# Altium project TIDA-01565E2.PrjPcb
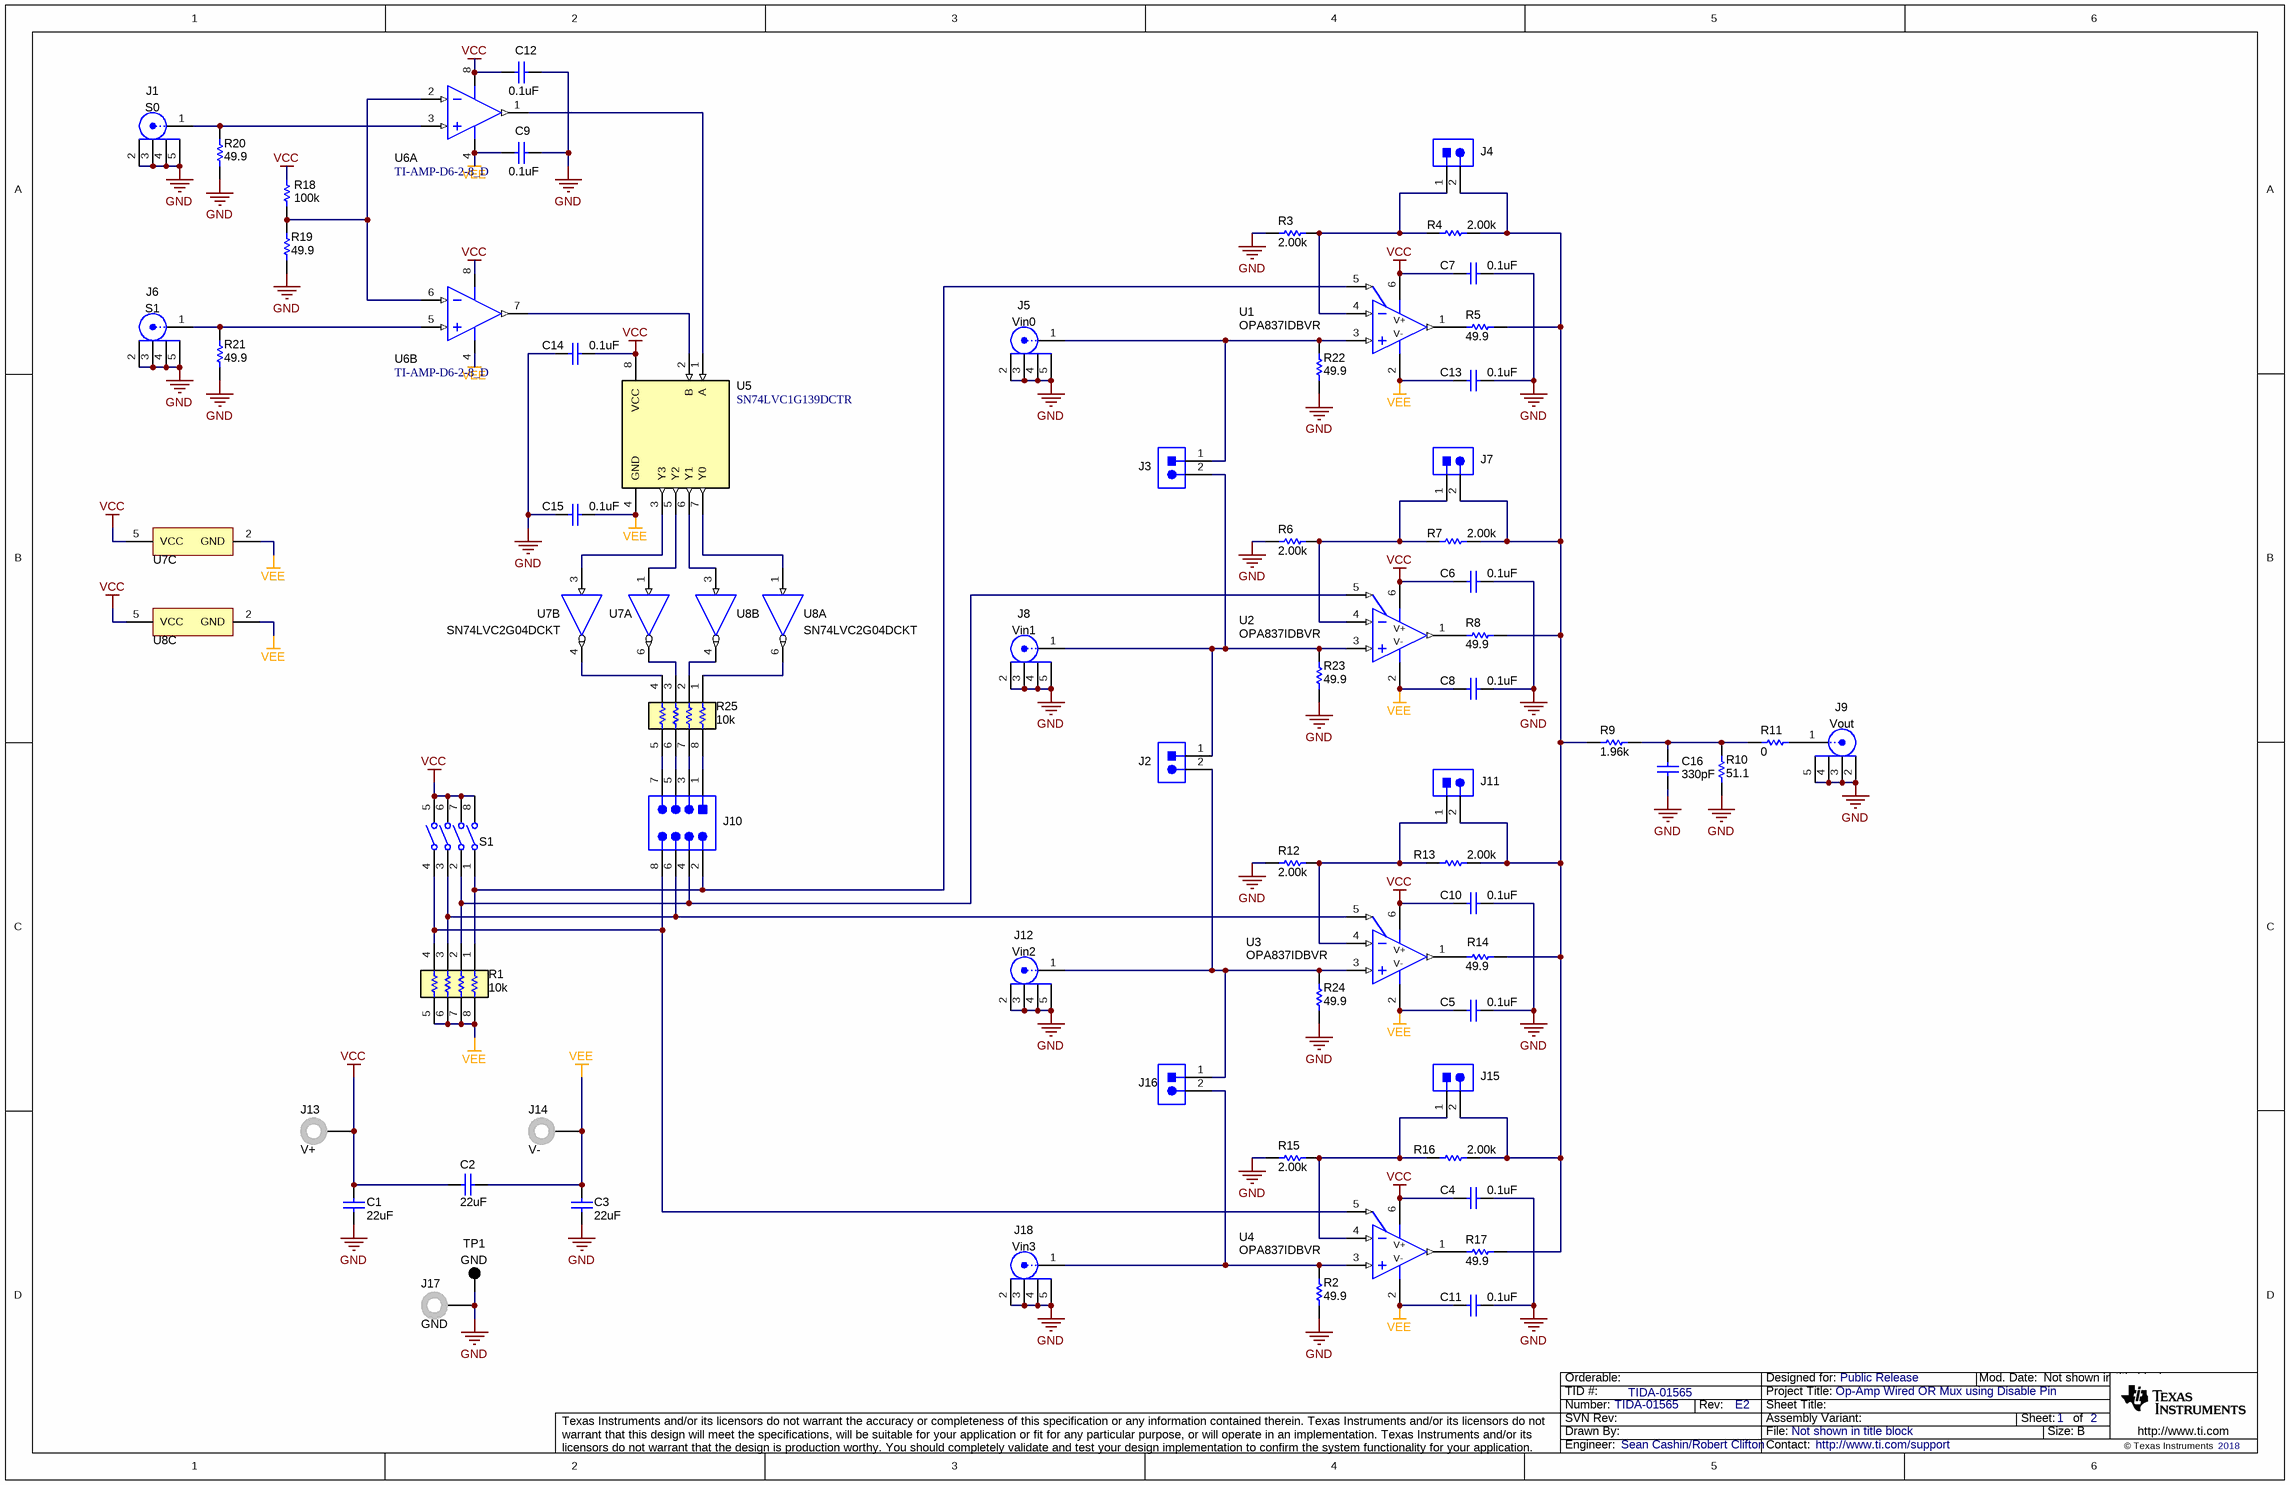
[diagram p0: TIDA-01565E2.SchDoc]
CopyrightYear: 2018; PCB_Layout: Bob Holtz; PCB_Rev: E2; PRJ_Customer: Public Release; PRJ_Engineer: Sean Cashin/Robert Clifton; PRJ_Number: TIDA-01565; PRJ_Title: Op-Amp Wired OR Mux using Disable Pin; SCH_Rev: E2; TechSupport: http://www.ti.com/support; TID: TIDA-01565
2 sheets, 106 parts. Net scope: global (net labels, ports and power ports of the same name join across sheets).
Board file: TIDA-01565E2.PcbDoc
Sheets:
  TIDA-01565E2.SchDoc
  TIDA-01565E2_Hardware.SchDoc

## Sheet TIDA-01565E2.SchDoc
size 431 x 279 mm; Date: Not shown in title block; ApprovedBy: Not shown in title block; CheckedBy: Not shown in title block; Author: Not shown in title block; CompanyName: Not shown in title block; Engineer: Not shown in title block; Organization: Not shown in title block; Address1: Not shown in title block; Address2: Not shown in title block; Address3: Not shown in title block; Address4: Not shown in title block; DocumentNumber: 1; Revision: Use project parameter SCH_Rev; SheetNumber: 1; SheetTotal: 2; PageSetup: Record=PageOptions¦CenterHorizontal=True¦CenterVertical=True¦PrintScale=1.00¦XCorrection=1.00¦YCorrection=1.00¦PrintKind=0¦BorderSize=5000000¦LeftOffset=0¦BottomOffset=0¦Orientation=2¦PaperLength=1000¦PaperWidth=1000¦Scale=100¦PaperSource=15¦PrintQuality=600¦MediaType=1¦DitherType=10¦PaperKind=Letter¦PrintScaleMode=1

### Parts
(Parts that share a designator on the sheet are numbered #1, #2 ... from top to bottom, then left to right.)
C1  ValueDisplayed: 22uF  [0603]  (hidden comment: Capacitor)
C2  ValueDisplayed: 22uF  [0603]  (hidden comment: Capacitor)
C3  ValueDisplayed: 22uF  [0603]  (hidden comment: Capacitor)
C4  ValueDisplayed: 0.1uF  [0402]  (hidden comment: Capacitor)
C5  ValueDisplayed: 0.1uF  [0402]  (hidden comment: Capacitor)
C6  ValueDisplayed: 0.1uF  [0402]  (hidden comment: Capacitor)
C7  ValueDisplayed: 0.1uF  [0402]  (hidden comment: Capacitor)
C8  ValueDisplayed: 0.1uF  [0402]  (hidden comment: Capacitor)
C9  ValueDisplayed: 0.1uF  [0402]  (hidden comment: Capacitor)
C10  ValueDisplayed: 0.1uF  [0402]  (hidden comment: Capacitor)
C11  ValueDisplayed: 0.1uF  [0402]  (hidden comment: Capacitor)
C12  ValueDisplayed: 0.1uF  [0402]  (hidden comment: Capacitor)
C13  ValueDisplayed: 0.1uF  [0402]  (hidden comment: Capacitor)
C14  ValueDisplayed: 0.1uF  [0402]  (hidden comment: Capacitor)
C15  ValueDisplayed: 0.1uF  [0402]  (hidden comment: Capacitor)
C16  ValueDisplayed: 330pF  [0603]  (hidden comment: Capacitor)
J1  S0  [Amphenol_901-10309]
J2  TSW-102-07-G-S  [TSW-102-07-X-S]  (value not drawn)
J3  TSW-102-07-G-S  [TSW-102-07-X-S]  (value not drawn)
J4  TSW-102-07-G-S  [TSW-102-07-X-S]  (value not drawn)
J5  Vin0  [Amphenol_901-10309]
J6  S1  [Amphenol_901-10309]
J7  TSW-102-07-G-S  [TSW-102-07-X-S]  (value not drawn)
J8  Vin1  [Amphenol_901-10309]
J9  Vout  [Amphenol_901-10309]
J10  TSW-104-07-G-D  [TSW-104-07-G-D]  (value not drawn)
J11  TSW-102-07-G-S  [TSW-102-07-X-S]  (value not drawn)
J12  Vin2  [Amphenol_901-10309]
J13  V+  [Keystone_6095]
J14  V-  [Keystone_6095]
J15  TSW-102-07-G-S  [TSW-102-07-X-S]  (value not drawn)
J16  TSW-102-07-G-S  [TSW-102-07-X-S]  (value not drawn)
J17  GND  [Keystone_6095]
J18  Vin3  [Amphenol_901-10309]
R1  ValueDisplayed: 10k  [TC164]  (hidden comment: RES_ARRAY_4x1)
R2  ValueDisplayed: 49.9  [0603]  (hidden comment: Resistor)
R3  ValueDisplayed: 2.00k  [0603]  (hidden comment: RT0603BRD072KL)
R4  ValueDisplayed: 2.00k  [0603]  (hidden comment: RT0603BRD072KL)
R5  ValueDisplayed: 49.9  [0603]  (hidden comment: Resistor)
R6  ValueDisplayed: 2.00k  [0603]  (hidden comment: RT0603BRD072KL)
R7  ValueDisplayed: 2.00k  [0603]  (hidden comment: RT0603BRD072KL)
R8  ValueDisplayed: 49.9  [0603]  (hidden comment: Resistor)
R9  ValueDisplayed: 1.96k  [0603]  (hidden comment: RC0603FR-071K96L)
R10  ValueDisplayed: 51.1  [0603]  (hidden comment: Resistor)
R11  ValueDisplayed: 0  [0603]  (hidden comment: RC0603JR-070RL)
R12  ValueDisplayed: 2.00k  [0603]  (hidden comment: RT0603BRD072KL)
R13  ValueDisplayed: 2.00k  [0603]  (hidden comment: RT0603BRD072KL)
R14  ValueDisplayed: 49.9  [0603]  (hidden comment: Resistor)
R15  ValueDisplayed: 2.00k  [0603]  (hidden comment: RT0603BRD072KL)
R16  ValueDisplayed: 2.00k  [0603]  (hidden comment: RT0603BRD072KL)
R17  ValueDisplayed: 49.9  [0603]  (hidden comment: Resistor)
R18  ValueDisplayed: 100k  [0603]  (hidden comment: Resistor)
R19  ValueDisplayed: 49.9  [0603]  (hidden comment: Resistor)
R20  ValueDisplayed: 49.9  [0603]  (hidden comment: Resistor)
R21  ValueDisplayed: 49.9  [0603]  (hidden comment: Resistor)
R22  ValueDisplayed: 49.9  [0603]  (hidden comment: Resistor)
R23  ValueDisplayed: 49.9  [0603]  (hidden comment: Resistor)
R24  ValueDisplayed: 49.9  [0603]  (hidden comment: Resistor)
R25  ValueDisplayed: 10k  [TC164]  (hidden comment: RES_ARRAY_4x1)
S1  SW_4SPST  [SW_219-4LPST]  (value not drawn)
TP1  GND  [Keystone5001]
U1  OPA837IDBVR  [DBV0006A_M]
U2  OPA837IDBVR  [DBV0006A_M]
U3  OPA837IDBVR  [DBV0006A_M]
U4  OPA837IDBVR  [DBV0006A_M]
U5  SN74LVC1G139DCTR  [DCT0008A_N]
U6  TI-AMP-D6-2-8_D  [D0008A_L]  (parts A,B of 2)
U7#1  SN74LVC2G04DCKT  [DCK0006A_N]  (value not drawn)  (part C of 3)
U7#2  SN74LVC2G04DCKT  [DCK0006A_N]  (value not drawn)  (parts A,B of 3)
U8#1  SN74LVC2G04DCKT  [DCK0006A_N]  (parts A,B of 3)
U8#2  SN74LVC2G04DCKT  [DCK0006A_N]  (value not drawn)  (part C of 3)

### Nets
GND: C1.2 C3.2 C4.2 C5.2 C6.2 C7.2 C8.2 C9.2 C10.2 C11.2 C12.2 C13.2 C14.1 C15.1 C16.2 J1.2 J1.3 J1.4 J1.5 J5.2 J5.3 J5.4 J5.5 J6.2 J6.3 J6.4 J6.5 J8.2 J8.3 J8.4 J8.5 J9.2 J9.3 J9.4 J9.5 J12.2 J12.3 J12.4 J12.5 J17.1 J18.2 J18.3 J18.4 J18.5 R2.1 R3.1 R6.1 R10.1 R12.1 R15.1 R19.1 R20.1 R21.1 R22.1 R23.1 R24.1 TP1.1
VCC: C1.1 C2.1 C4.1 C6.1 C7.1 C10.1 C12.1 C14.2 J13.1 R18.1 S1.5(B4) S1.6(B3) S1.7(B2) S1.8(B1) U1.6(V+) U2.6(V+) U3.6(V+) U4.6(V+) U5.8(VCC) U6.8(VCC+) U7#1.5(VCC) U8#2.5(VCC)
VEE: C2.2 C3.1 C5.1 C8.1 C9.1 C11.1 C13.1 C15.2 J14.1 R1.5 R1.6 R1.7 R1.8 U1.2(V-) U2.2(V-) U3.2(V-) U4.2(V-) U5.4(GND) U6.4(VCC-) U7#1.2(GND) U8#2.2(GND)
NetC16_1: C16.1 R9.2 R10.2 R11.1
NetJ1_1: J1.1 R20.2 U6.3(IN1+)
NetJ2_1: J2.1 J3.2 J8.1 R23.2 U2.3(IN+)
NetJ2_2: J2.2 J12.1 J16.1 R24.2 U3.3(IN+)
NetJ3_1: J3.1 J5.1 R22.2 U1.3(IN+)
NetJ4_1: J4.1 R3.2 R4.1 U1.4(IN-)
NetJ4_2: J4.2 J7.2 J11.2 J15.2 R4.2 R5.2 R7.2 R8.2 R9.1 R13.2 R14.2 R16.2 R17.2
NetJ6_1: J6.1 R21.2 U6.5(IN2+)
NetJ7_1: J7.1 R6.2 R7.1 U2.4(IN-)
NetJ9_1: J9.1 R11.2
NetJ10_1: J10.1 R25.8
NetJ10_2: J10.2 R1.1 S1.1(A1) U1.5(PD)
NetJ10_3: J10.3 R25.7
NetJ10_4: J10.4 R1.2 S1.2(A2) U2.5(PD)
NetJ10_5: J10.5 R25.6
NetJ10_6: J10.6 R1.3 S1.3(A3) U3.5(PD)
NetJ10_7: J10.7 R25.5
NetJ10_8: J10.8 R1.4 S1.4(A4) U4.5(PD)
NetJ11_1: J11.1 R12.2 R13.1 U3.4(IN-)
NetJ15_1: J15.1 R15.2 R16.1 U4.4(IN-)
NetJ16_2: J16.2 J18.1 R2.2 U4.3(IN+)
NetR5_1: R5.1 U1.1(OUT)
NetR8_1: R8.1 U2.1(OUT)
NetR14_1: R14.1 U3.1(OUT)
NetR17_1: R17.1 U4.1(OUT)
NetR18_2: R18.2 R19.2 U6.2(IN1-) U6.6(IN2-)
NetR25_1: R25.1 U8#1.6(1Y)
NetR25_2: R25.2 U8#1.4(2Y)
NetR25_3: R25.3 U7#2.6(1Y)
NetR25_4: R25.4 U7#2.4(2Y)
NetU5_1: U5.1(A) U6.1(OUT1)
NetU5_2: U5.2(B) U6.7(OUT2)
NetU5_3: U5.3(Y3) U7#2.3(2A)
NetU5_5: U5.5(Y2) U7#2.1(1A)
NetU5_6: U5.6(Y1) U8#1.3(2A)
NetU5_7: U5.7(Y0) U8#1.1(1A)

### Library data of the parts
C1-C3 = CMP-0007158-5: CAP, CERM, 22 uF, 10 V, +/- 20%, X5R, 0603; PartNumber: GRM187R61A226ME15D; Manufacturer: MuRata; Polarized: N; Value: 22uF; U/M: EA; Cap_F: 22µF; Value1: Unknown; VDC_V: 10V; TaMin_C: -55°C; TaMax_C: 85°C; SizeArea_mm2: 1.28; SizeAreaWB_mm2: 4.68; SizeX_mm: 1.6; SizeY_mm: 0.8; SizeZ_mm: 1; AEC Category: Q200
C4-C15 = CMP-0006259-2: CAP, CERM, 0.1 uF, 10 V, +/- 10%, X5R, 0402; PartNumber: C1005X5R1A104K050BA; Manufacturer: TDK; Polarized: N; Value: 0.1uF; U/M: EA; Cap_F: 100nF; Value1: Unknown; VDC_V: 10V; TaMin_C: -55°C; TaMax_C: 85°C; SizeArea_mm2: 0.5; SizeAreaWB_mm2: 3; SizeX_mm: 1; SizeZ_mm: 0.6; AEC Category: Q200
C16 = CMP-0006784-4: CAP, CERM, 330 pF, 50 V, +/- 5%, C0G/NP0, 0603; PartNumber: 06035A331JAT2A; Manufacturer: AVX; Polarized: N; Value: 330pF; U/M: EA; ESR_ohm: 0.071; Value1: 0.071 ohm; VDC_V: 50V; TaMin_C: -55°C; TaMax_C: 125°C; SizeArea_mm2: 1.28; SizeAreaWB_mm2: 4.68; SizeX_mm: 1.6; SizeY_mm: 0.8; SizeZ_mm: 1; AEC Category: Q200
J1 J5 J6 J8 J9 J12 J18 = CMP-0055840-1: SMA JACK 50 OHM EDGE MNT, SMT; Manufacturer: Amphenol-Tuchel Electronics; PartNumber: 901-10309; CNHeader: FALSE; ContactFinish: Gold; CT: TRUE
J2-J4 J7 J11 J15 J16 = CMP-0075405-1: Header, 100mil, 2x1, Gold, TH; Manufacturer: Samtec; Pitch_mm: 2.54; Cert_VDE: N; Gender: Male; Cert_CSA: Y; Voltage_V: 550V; Green_REACh: Passed; Current_A: 6.3A; CT: False; Green_Lifecycle: Active; Row_Count: 1; CNHeader: True
J10 = CMP-0075408-1: Header, 100mil, 4x2, Gold, TH; Manufacturer: Samtec; Pitch_mm: 2.54; Cert_VDE: N; Gender: Male; Cert_CSA: Y; Voltage_V: 550V; Green_REACh: Passed; Current_A: 6.3A; CT: False; Green_Lifecycle: Active; Row_Count: 2; CNHeader: True
J13 J14 J17 = CMP-0055169-2: Standard Banana Jack, Uninsulated; Manufacturer: Keystone; CT: TRUE; Green_REACh: Passed; CNHeader: FALSE; Green_Lifecycle: Active
R1 R25 = CMP-0015378-3: RES, 10 k, 5%, 0.0625 W, 3.2x1.6mm; PartNumber: TC164-JR-0710KL; Manufacturer: Yageo America; CompType: Resistor; Value: 10k; Value_Code: 10k0; Power_W: 62.5mW; TempCo: 200 ppm/C; EIA_Code: E24; U/M: EA; AEC Category: Q200; AEC Qualified: N
R2 R5 R8 R14 R17 R19-R24 = CMP-0022707-2: RES, 49.9, 1%, 0.1 W, AEC-Q200 Grade 0, 0603; PartNumber: ERJ-3EKF49R9V; Manufacturer: Panasonic; Value: 49.9; Value_Code: 49R9; Power_W: 100mW; Value2: 0.1W; TempCo: 100 ppm/C; SizeArea_mm2: 1.28; SizeX_mm: 1.6; SizeY_mm: 0.8; SizeZ_mm: 1; EIA_Code: E96; U/M: EA; AEC Category: Q200; AEC Qualified: Y; AEC Grade: 0
R3 R4 R6 R7 R12 R13 R15 R16 = CMP-0024089-3: RES, 2.00 k, 0.1%, 0.1 W, 0603; Manufacturer: Yageo America; Power_W: 100mW; TempCo: 25 ppm/C; Value_Code: 2k00; U/M: EA; Value: 2.00k; EIA_Code: E192; Res_ohm: 2k; SizeX_mm: 1.6; SizeY_mm: 0.8; SizeZ_mm: 1; Value2: 0.1W; SizeArea_mm2: 1.28; CompType: Resistor; VDC_V: 75V; AEC Category: Q200
R9 = CMP-0022894-3: RES, 1.96 k, 1%, 0.1 W, 0603; Manufacturer: Yageo America; Power_W: 100mW; TempCo: 200 ppm/C; Value_Code: 1k96; U/M: EA; Value: 1.96k; EIA_Code: E96; SizeX_mm: 1.6; SizeY_mm: 0.8; SizeZ_mm: 1; Value2: 0.1W; SizeArea_mm2: 1.28; CompType: Resistor; VDC_V: 150V; AEC Category: Q200
R10 = CMP-0023168-3: RES, 51.1, 1%, 0.1 W, 0603; PartNumber: RC0603FR-0751R1L; Manufacturer: Yageo America; Value: 51.1; Value_Code: 51R1; Power_W: 100mW; Value2: 0.1W; VDC_V: 150V; TempCo: 200 ppm/C; SizeArea_mm2: 1.28; SizeX_mm: 1.6; SizeY_mm: 0.8; SizeZ_mm: 1; EIA_Code: E96; U/M: EA; AEC Category: Q200
R11 = CMP-0025885-3: RES, 0, 5%, 0.1 W, 0603; Manufacturer: Yageo America; Power_W: 100mW; TempCo: 200 ppm/C; Value_Code: 0000; U/M: EA; Value: 0; EIA_Code: E24; SizeX_mm: 1.6; SizeZ_mm: 1; Value2: 0.1W; SizeArea_mm2: 1.28; CompType: Resistor; VDC_V: 50V; AEC Category: Q200; SizeY_mm: 0.8
R18 = CMP-0023630-3: RES, 100 k, 0.1%, 0.1 W, 0603; PartNumber: RT0603BRD07100KL; Manufacturer: Yageo America; Value: 100k; Power_W: 100mW; Value2: 0.1W; VDC_V: 75V; TempCo: 25 ppm/C; SizeArea_mm2: 1.28; SizeX_mm: 1.6; SizeY_mm: 0.8; SizeZ_mm: 1; EIA_Code: E192; U/M: EA; AEC Category: Q200
S1 = CMP-0002176-2: Switch, SPST 4 Pos, Top Actuated, SMT; PartNumber: 219-4LPST; Manufacturer: CTS Electrocomponents; VDC_V: 50V; SwitchFunction: Off-On; PositionCount: 4; CurrentRating_mA: 100A
TP1 = CMP-0055138-1: Test Point, Miniature, Black, TH; Manufacturer: Keystone; CNHeader: FALSE; Green_Lifecycle: Active; Green_REACh: Passed; ContactFinish: Silver; CT: TRUE
U1-U4 = CMP-0013237-2: Low Power, Precision, 105MHz, Voltage Feedback Op Amp, DBV0006A (SOT-6); Manufacturer: Texas Instruments; Alternate PartNumber: OPA837IDBVT; SizeX_mm: 2.8; SizeY_mm: 2.9; CompType: IC; SizeZ_mm: 1.45; SizeArea_mm2: 8.12; SizeAreaWB_mm2: 14.82; U/M: EA
U5 = CMP-0050973-1: 2-Line-to-4-Line Decoder, DCT0008A, LARGE T&R; Manufacturer: Texas Instruments; Bits(#): 1; Output Drive (IOL/IOH)(Max)(mA): 32/-32; Technology Family: LVC; tpd @ Nom Voltage(Max)(ns): 16.5,7.5,4.9,3.6; Rating: Catalog; Input Type: CMOS/TTL; F @ Nom Voltage(Max)(Mhz): 150; Voltage(Nom)(V): 1.8,2.5,3.3,5; Specialty Logic Family: Decoder/Encoder/Multiplexer; Schmitt Trigger: No; ICC @ Nom Voltage(Max)(mA): 0.01; Output Type: CMOS; VCC(Min)(V): 1.65; Logic: True; VCC(Max)(V): 5.5
U6 = CMP-0043405-1: Dual High-Performance, Low-Voltage Operational Amplifier, 2 to 5 V, -40 to 85 degC, 8-pin SOIC (D8), Green (RoHS & no Sb/Br); PartNumber: TLV2362ID; Manufacturer: Texas Instruments; CMRR(Min)(dB): 75; GBW(Typ)(MHz): 6; IIB(Max)(pA): 150000; Iq per channel(Max)(mA): 2.25; Number of Channels: 2; Slew Rate(Typ)(V/us): 2.5; Sub Family: General Purpose Amplifier, Low Noise Amp (<=10nV/rtHz), Low Supply Voltage Amplifier (<=2.7V); Total Supply Voltage(Max)(+5V is 5, +/-5V is 10): 5; Vn at 1kHz(Typ)(nV/rtHz): 9
U7#1 U7#2 U8#1 U8#2 = CMP-0051888-2: Dual Inverter, DCK0006A, SMALL T&R; Manufacturer: Texas Instruments; Output Type: CMOS; Bits(#): 2; Input Type: CMOS/TTL; Technology Family: LVC; Schmitt Trigger: No; VCC(Max)(V): 5.5; Sub-Family: Inverting Buffer/Driver; Rating: Catalog; Output Drive (IOL/IOH)(Max)(mA): 32/-32; ICC @ Nom Voltage(Max)(mA): 0.01; VCC(Min)(V): 1.65; F @ Nom Voltage(Max)(Mhz): 150; Logic: Inverting; Voltage(Nom)(V): 1.8,2.5,3.3,5; tpd @ Nom Voltage(Max)(ns): 8,4.9,4.6,3.7

## Sheet TIDA-01565E2_Hardware.SchDoc
size 431 x 279 mm; Date: Not shown in title block; ApprovedBy: Not shown in title block; CheckedBy: Not shown in title block; Author: Not shown in title block; CompanyName: Not shown in title block; Engineer: Not shown in title block; Organization: Not shown in title block; Address1: Not shown in title block; Address2: Not shown in title block; Address3: Not shown in title block; Address4: Not shown in title block; DocumentNumber: 2; Revision: Use project parameter SCH_Rev; SheetNumber: 2; SheetTotal: 2; PageSetup: Record=PageOptions¦CenterHorizontal=True¦CenterVertical=True¦PrintScale=1.00¦XCorrection=1.00¦YCorrection=1.00¦PrintKind=0¦BorderSize=5000000¦LeftOffset=0¦BottomOffset=0¦Orientation=2¦PaperLength=1000¦PaperWidth=1000¦Scale=100¦PaperSource=15¦PrintQuality=600¦MediaType=1¦DitherType=10¦PaperKind=Letter¦PrintScaleMode=1
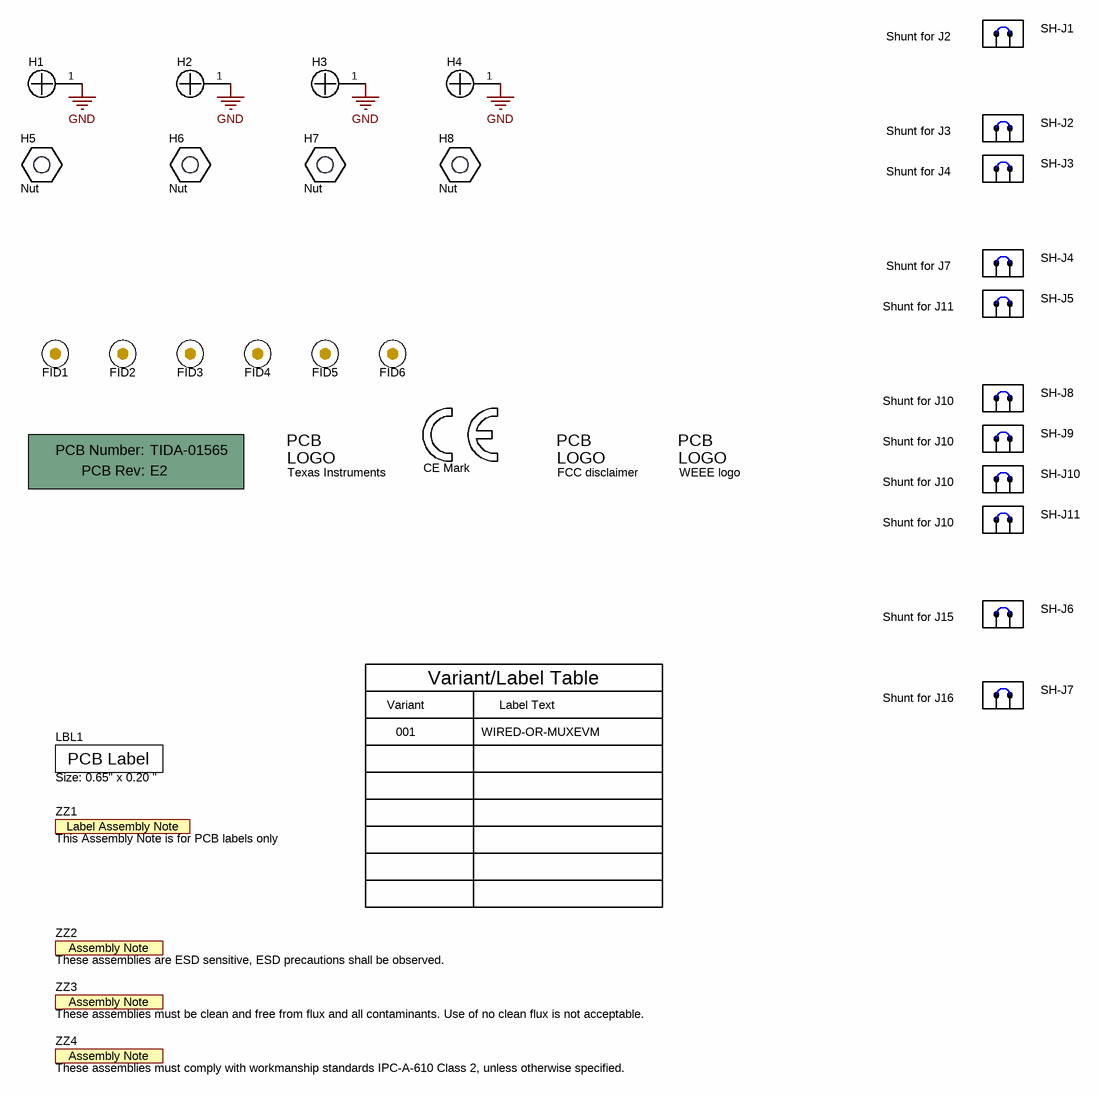
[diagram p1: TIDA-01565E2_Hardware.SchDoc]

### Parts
!PCB  Printed Circuit Board  (value not drawn)  (mechanical)
FID1  Fiducial  [Fiducial10-20]  (value not drawn)
FID2  Fiducial  [Fiducial10-20]  (value not drawn)
FID3  Fiducial  [Fiducial10-20]  (value not drawn)
FID4  Fiducial  [Fiducial10-20]  (value not drawn)
FID5  Fiducial  [Fiducial10-20]  (value not drawn)
FID6  Fiducial  [Fiducial10-20]  (value not drawn)
H1  NY PMS 440 0025 PH  [NY PMS 440 0025 PH]  (value not drawn)
H2  NY PMS 440 0025 PH  [NY PMS 440 0025 PH]  (value not drawn)
H3  NY PMS 440 0025 PH  [NY PMS 440 0025 PH]  (value not drawn)
H4  NY PMS 440 0025 PH  [NY PMS 440 0025 PH]  (value not drawn)
H5  Nut  [Keystone_1902C]
H6  Nut  [Keystone_1902C]
H7  Nut  [Keystone_1902C]
H8  Nut  [Keystone_1902C]
LBL1  Size: 0.65" x 0.20 "  [Label_650x200]
Logo1  Texas Instruments  [TI_Stacked_Overlay_Small]  (no BOM)
Logo2  CE Mark  [CE_Mark_5mm]  (no BOM)
Logo3  FCC disclaimer  [FCC_disclaimer]  (no BOM)
Logo4  WEEE logo  [WEEE_Minimum]  (no BOM)
SH-J1  382811-6  (value not drawn)  (mechanical)
SH-J2  382811-6  (value not drawn)  (mechanical)
SH-J3  382811-6  (value not drawn)  (mechanical)
SH-J4  382811-6  (value not drawn)  (mechanical)
SH-J5  382811-6  (value not drawn)  (mechanical)
SH-J6  382811-6  (value not drawn)  (mechanical)
SH-J7  382811-6  (value not drawn)  (mechanical)
SH-J8  382811-6  (value not drawn)  (mechanical)
SH-J9  382811-6  (value not drawn)  (mechanical)
SH-J10  382811-6  (value not drawn)  (mechanical)
SH-J11  382811-6  (value not drawn)  (mechanical)
ZZ1  This Assembly Note is for PCB labels only  [AssemblyNoteLabel]  (no BOM)
ZZ2  These assemblies are ESD sensitive, ESD precautions shall be observed.  [AssemblyNote]  (no BOM)
ZZ3  These assemblies must be clean and free from flux and all contaminants. Use of no clean flux is not acceptable.  [AssemblyNote]  (no BOM)
ZZ4  These assemblies must comply with workmanship standards IPC-A-610 Class 2, unless otherwise specified.  [AssemblyNote]  (no BOM)

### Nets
GND: H1.1 H2.1 H3.1 H4.1

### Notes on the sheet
- Shunt for J2
- Shunt for J3
- Shunt for J4
- Shunt for J7
- Shunt for J11
- Shunt for J10
- Variant/Label Table
- (near SH-J6) Shunt for J15
- Variant
- 001
- Label Text
- WIRED-OR-MUXEVM
- (near SH-J7) Shunt for J16

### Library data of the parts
!PCB = CMP-0003618-2: Manufacturer: Any; PartNumber: TIDA-01565
FID1-FID6 = CMP-0077181-1: Fiducial mark.  There is nothing to buy or mount.
H1-H4 = CMP-0003617-1: Machine Screw, Round, #4-40 x 1/4, Nylon, Philips panhead; Manufacturer: B&F Fastener Supply; CompType: Hardware
H5-H8 = CMP-0003610-1: Standoff, Hex, 0.5"L #4-40 Nylon; Manufacturer: Keystone; PartNumber: 1902C; CompType: Hardware
LBL1 = CMP-0003625-1: Thermal Transfer Printable Labels, 0.650" W x 0.200" H - 10,000 per roll; Manufacturer: Brady; Key: THT-14-423-10; CompType: Label
Logo1 = CMP-0074838-1: Texas Instrument Corporate Signature; SymbolCreator: a0412235; Lib Reference: TI_Logo; Library Reference: Logo
Logo2 = CMP-0074844-1: SymbolCreator: a0412235
Logo3 = CMP-0074847-1: FCC_disclaimer; Library Reference: Logo
Logo4 = CMP-0074769-1
SH-J1-SH-J11 = CMP-0003613-1: Shunt, 100mil, Gold plated, Black; Manufacturer: AMP; Value: 1x2; Note: You can "mate" this to a header by matching the designator.  i.e. use SH-J3 for header J3
ZZ1 = CMP-0003616-3
ZZ2 = CMP-0077236-1
ZZ3 = CMP-0077237-1
ZZ4 = CMP-0077238-1

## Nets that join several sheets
GND: TIDA-01565E2 (57 pins), TIDA-01565E2_Hardware (H1.1 H2.1 H3.1 H4.1)

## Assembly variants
001: not fitted C16 FID1 FID2 FID3 FID4 FID5 FID6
